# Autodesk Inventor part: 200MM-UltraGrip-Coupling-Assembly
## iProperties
Created: 2012-05
Part Number: 200MM-UltraGrip-Coupling-Assembly
Document SubType Name: Modeling
Designer: D Cole
Density: 1 g/cm^3
Author: D Cole
